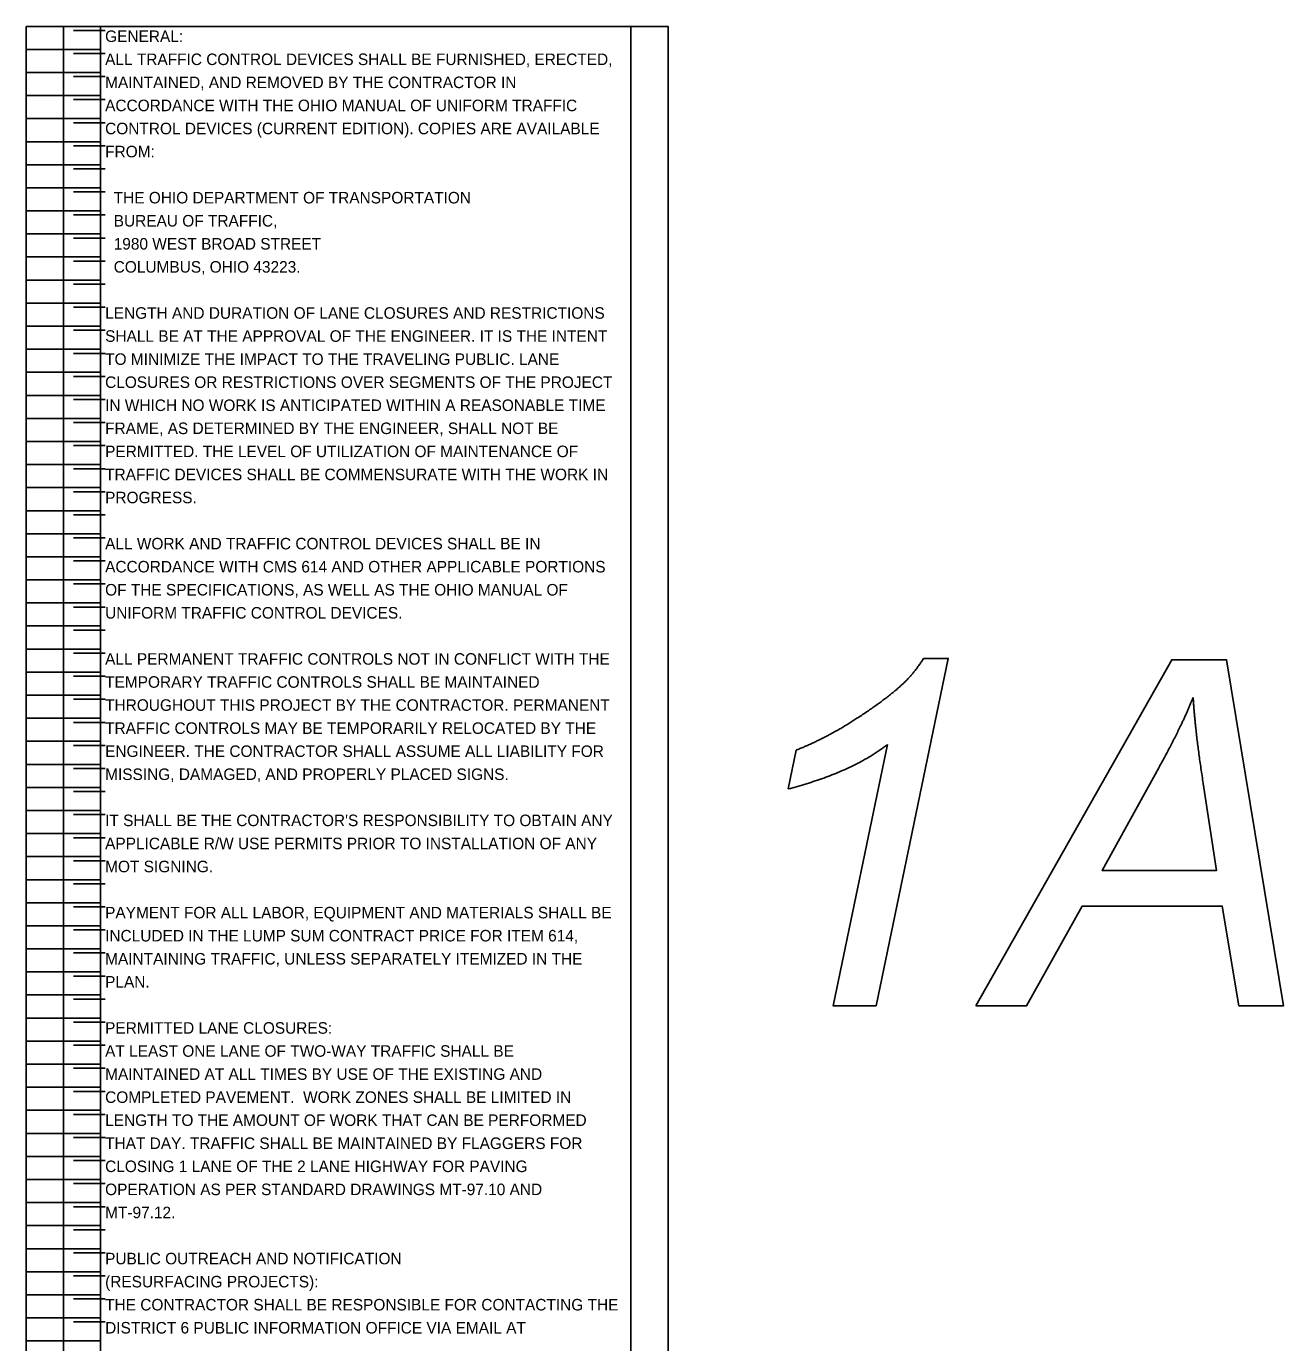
# Model space of a CAD drawing. Extents: x 12522 to 12538, y 1124 to 1850.
# Drawn here: x 12521.92 to 12537.18, y 1833.81 to 1849.79 of the extents above; entities that cross this region are included whole.
import ezdxf

# ---------------------------------------------------------------- set-up
doc = ezdxf.new("R2010")
doc.units = 0
doc.layers.add('SC_Scratch1', color=7, linetype='Continuous')
doc.layers.add('SH_Text', color=7, linetype='Continuous')

msp = doc.modelspace()

# ---------------------------------------------------------------- linework, layer by layer
at = {"layer": 'SC_Scratch1'}
for p, q in [((12521.919, 1829.631), (12521.919, 1849.791)), ((12521.919, 1849.791), (12522.819, 1849.791)), ((12522.876, 1849.741), (12522.492, 1849.741)), ((12522.819, 1829.631), (12522.819, 1849.791)), ((12522.819, 1849.791), (12529.259, 1849.791)), ((12522.819, 1829.631), (12522.819, 1849.791)), ((12522.819, 1849.791), (12522.819, 1829.631)), ((12529.259, 1849.791), (12529.259, 1829.631)), ((12521.919, 1849.511), (12522.819, 1849.511)), ((12522.876, 1849.461), (12522.492, 1849.461)), ((12521.919, 1849.231), (12522.819, 1849.231)), ((12522.876, 1849.181), (12522.492, 1849.181)), ((12521.919, 1848.951), (12522.819, 1848.951)), ((12522.876, 1848.901), (12522.492, 1848.901)), ((12521.919, 1848.671), (12522.819, 1848.671)), ((12522.876, 1848.621), (12522.492, 1848.621)), ((12521.919, 1848.391), (12522.819, 1848.391)), ((12522.876, 1848.341), (12522.492, 1848.341)), ((12521.919, 1848.111), (12522.819, 1848.111)), ((12522.876, 1848.061), (12522.492, 1848.061)), ((12521.919, 1847.831), (12522.819, 1847.831)), ((12522.876, 1847.781), (12522.492, 1847.781)), ((12521.919, 1847.551), (12522.819, 1847.551)), ((12522.876, 1847.501), (12522.492, 1847.501)), ((12521.919, 1847.271), (12522.819, 1847.271)), ((12522.876, 1847.221), (12522.492, 1847.221)), ((12521.919, 1846.991), (12522.819, 1846.991)), ((12522.876, 1846.941), (12522.492, 1846.941)), ((12521.919, 1846.711), (12522.819, 1846.711)), ((12522.876, 1846.661), (12522.492, 1846.661)), ((12521.919, 1846.431), (12522.819, 1846.431)), ((12522.876, 1846.381), (12522.492, 1846.381)), ((12521.919, 1846.151), (12522.819, 1846.151)), ((12522.876, 1846.101), (12522.492, 1846.101)), ((12521.919, 1845.871), (12522.819, 1845.871)), ((12522.876, 1845.821), (12522.492, 1845.821)), ((12521.919, 1845.591), (12522.819, 1845.591)), ((12522.876, 1845.541), (12522.492, 1845.541)), ((12521.919, 1845.311), (12522.819, 1845.311)), ((12522.876, 1845.261), (12522.492, 1845.261)), ((12521.919, 1845.031), (12522.819, 1845.031)), ((12522.876, 1844.981), (12522.492, 1844.981)), ((12521.919, 1844.751), (12522.819, 1844.751)), ((12522.876, 1844.701), (12522.492, 1844.701)), ((12521.919, 1844.471), (12522.819, 1844.471)), ((12522.876, 1844.421), (12522.492, 1844.421)), ((12521.919, 1844.191), (12522.819, 1844.191)), ((12522.876, 1844.141), (12522.492, 1844.141)), ((12521.919, 1843.911), (12522.819, 1843.911)), ((12522.876, 1843.861), (12522.492, 1843.861)), ((12521.919, 1843.631), (12522.819, 1843.631)), ((12522.876, 1843.581), (12522.492, 1843.581)), ((12521.919, 1843.351), (12522.819, 1843.351)), ((12522.876, 1843.301), (12522.492, 1843.301)), ((12521.919, 1843.071), (12522.819, 1843.071)), ((12522.876, 1843.021), (12522.492, 1843.021)), ((12521.919, 1842.791), (12522.819, 1842.791)), ((12522.876, 1842.741), (12522.492, 1842.741)), ((12521.919, 1842.511), (12522.819, 1842.511)), ((12522.876, 1842.461), (12522.492, 1842.461)), ((12521.919, 1842.231), (12522.819, 1842.231)), ((12522.876, 1842.181), (12522.492, 1842.181)), ((12521.919, 1841.951), (12522.819, 1841.951)), ((12522.876, 1841.901), (12522.492, 1841.901)), ((12521.919, 1841.671), (12522.819, 1841.671)), ((12522.876, 1841.621), (12522.492, 1841.621)), ((12521.919, 1841.391), (12522.819, 1841.391)), ((12522.876, 1841.341), (12522.492, 1841.341)), ((12521.919, 1841.111), (12522.819, 1841.111)), ((12522.876, 1841.061), (12522.492, 1841.061)), ((12531.166, 1840.532), (12531.263, 1841.003)), ((12521.919, 1840.831), (12522.819, 1840.831)), ((12522.876, 1840.781), (12522.492, 1840.781)), ((12521.919, 1840.551), (12522.819, 1840.551)), ((12522.876, 1840.501), (12522.492, 1840.501)), ((12521.919, 1840.271), (12522.819, 1840.271)), ((12522.876, 1840.221), (12522.492, 1840.221)), ((12521.919, 1839.991), (12522.819, 1839.991)), ((12522.876, 1839.941), (12522.492, 1839.941)), ((12521.919, 1839.711), (12522.819, 1839.711)), ((12522.876, 1839.661), (12522.492, 1839.661)), ((12521.919, 1839.431), (12522.819, 1839.431)), ((12522.876, 1839.381), (12522.492, 1839.381)), ((12521.919, 1839.151), (12522.819, 1839.151)), ((12522.876, 1839.101), (12522.492, 1839.101)), ((12521.919, 1838.871), (12522.819, 1838.871)), ((12522.876, 1838.821), (12522.492, 1838.821)), ((12521.919, 1838.591), (12522.819, 1838.591)), ((12522.876, 1838.541), (12522.492, 1838.541)), ((12521.919, 1838.311), (12522.819, 1838.311)), ((12522.876, 1838.261), (12522.492, 1838.261)), ((12521.919, 1838.031), (12522.819, 1838.031)), ((12522.876, 1837.981), (12522.492, 1837.981)), ((12521.919, 1837.751), (12522.819, 1837.751)), ((12522.876, 1837.701), (12522.492, 1837.701)), ((12521.919, 1837.471), (12522.819, 1837.471)), ((12522.876, 1837.421), (12522.492, 1837.421)), ((12521.919, 1837.191), (12522.819, 1837.191)), ((12522.876, 1837.141), (12522.492, 1837.141)), ((12521.919, 1836.911), (12522.819, 1836.911)), ((12522.876, 1836.861), (12522.492, 1836.861)), ((12521.919, 1836.631), (12522.819, 1836.631)), ((12522.876, 1836.581), (12522.492, 1836.581)), ((12521.919, 1836.351), (12522.819, 1836.351)), ((12522.876, 1836.301), (12522.492, 1836.301)), ((12521.919, 1836.071), (12522.819, 1836.071)), ((12522.876, 1836.021), (12522.492, 1836.021)), ((12521.919, 1835.791), (12522.819, 1835.791)), ((12522.876, 1835.741), (12522.492, 1835.741)), ((12521.919, 1835.511), (12522.819, 1835.511)), ((12522.876, 1835.461), (12522.492, 1835.461)), ((12521.919, 1835.231), (12522.819, 1835.231)), ((12522.876, 1835.181), (12522.492, 1835.181)), ((12521.919, 1834.951), (12522.819, 1834.951)), ((12522.876, 1834.901), (12522.492, 1834.901)), ((12521.919, 1834.671), (12522.819, 1834.671)), ((12522.876, 1834.621), (12522.492, 1834.621)), ((12521.919, 1834.391), (12522.819, 1834.391)), ((12522.876, 1834.341), (12522.492, 1834.341)), ((12521.919, 1834.111), (12522.819, 1834.111)), ((12522.876, 1834.061), (12522.492, 1834.061)), ((12521.919, 1833.831), (12522.819, 1833.831))]:
    msp.add_line(p, q, dxfattribs=at)
for points in [[(12522.369, 1849.791), (12529.709, 1849.791), (12529.709, 1829.631), (12522.369, 1829.631)], [(12533.445, 1837.901), (12534.061, 1837.901), (12534.737, 1839.111), (12536.436, 1839.111), (12536.638, 1837.901), (12537.182, 1837.901), (12536.489, 1842.101), (12535.824, 1842.101)]]:
    msp.add_lwpolyline(points, close=True, dxfattribs=at)
for points in [[(12532.811, 1842.117), (12533.111, 1842.117), (12532.234, 1837.901), (12531.712, 1837.901), (12532.375, 1841.074)], [(12536.206, 1840.598), (12536.369, 1839.543), (12534.979, 1839.543), (12535.665, 1840.787)]]:
    msp.add_lwpolyline(points, dxfattribs=at)
for points in [[(12532.593, 1841.84), (12532.707, 1841.954), (12532.811, 1842.117)], [(12532.027, 1841.406), (12532.404, 1841.654), (12532.593, 1841.84)], [(12535.665, 1840.787), (12535.94, 1841.282), (12536.084, 1841.643)], [(12536.084, 1841.643), (12536.108, 1841.225), (12536.206, 1840.598)], [(12531.263, 1841.003), (12531.65, 1841.157), (12532.027, 1841.406)], [(12532.375, 1841.074), (12531.945, 1840.736), (12531.166, 1840.532)]]:
    msp.add_open_spline(points, degree=2, dxfattribs=at)

# ---------------------------------------------------------------- texts
at = {"layer": 'SH_Text'}
for s, p in [('GENERAL:', (12522.876, 1849.601)), ('ALL TRAFFIC CONTROL DEVICES SHALL BE FURNISHED, ERECTED,', (12522.876, 1849.321)), ('MAINTAINED, AND REMOVED BY THE CONTRACTOR IN ', (12522.876, 1849.041)), ('ACCORDANCE WITH THE OHIO MANUAL OF UNIFORM TRAFFIC ', (12522.876, 1848.761)), ('CONTROL DEVICES (CURRENT EDITION). COPIES ARE AVAILABLE ', (12522.876, 1848.481)), ('FROM: ', (12522.876, 1848.201)), ('  THE OHIO DEPARTMENT OF TRANSPORTATION ', (12522.876, 1847.641)), ('  BUREAU OF TRAFFIC, ', (12522.876, 1847.361)), ('  1980 WEST BROAD STREET ', (12522.876, 1847.081)), ('  COLUMBUS, OHIO 43223.', (12522.876, 1846.801)), ('LENGTH AND DURATION OF LANE CLOSURES AND RESTRICTIONS ', (12522.876, 1846.241)), ('SHALL BE AT THE APPROVAL OF THE ENGINEER. IT IS THE INTENT ', (12522.876, 1845.961)), ('TO MINIMIZE THE IMPACT TO THE TRAVELING PUBLIC. LANE ', (12522.876, 1845.681)), ('CLOSURES OR RESTRICTIONS OVER SEGMENTS OF THE PROJECT ', (12522.876, 1845.401)), ('IN WHICH NO WORK IS ANTICIPATED WITHIN A REASONABLE TIME ', (12522.876, 1845.121)), ('FRAME, AS DETERMINED BY THE ENGINEER, SHALL NOT BE ', (12522.876, 1844.841)), ('PERMITTED. THE LEVEL OF UTILIZATION OF MAINTENANCE OF ', (12522.876, 1844.561)), ('TRAFFIC DEVICES SHALL BE COMMENSURATE WITH THE WORK IN ', (12522.876, 1844.281)), ('PROGRESS.', (12522.876, 1844.001)), ('ALL WORK AND TRAFFIC CONTROL DEVICES SHALL BE IN ', (12522.876, 1843.441)), ('ACCORDANCE WITH CMS 614 AND OTHER APPLICABLE PORTIONS ', (12522.876, 1843.161)), ('OF THE SPECIFICATIONS, AS WELL AS THE OHIO MANUAL OF ', (12522.876, 1842.881)), ('UNIFORM TRAFFIC CONTROL DEVICES.', (12522.876, 1842.601)), ('ALL PERMANENT TRAFFIC CONTROLS NOT IN CONFLICT WITH THE ', (12522.876, 1842.041)), ('TEMPORARY TRAFFIC CONTROLS SHALL BE MAINTAINED ', (12522.876, 1841.761)), ('THROUGHOUT THIS PROJECT BY THE CONTRACTOR. PERMANENT ', (12522.876, 1841.481)), ('TRAFFIC CONTROLS MAY BE TEMPORARILY RELOCATED BY THE ', (12522.876, 1841.201)), ('ENGINEER. THE CONTRACTOR SHALL ASSUME ALL LIABILITY FOR ', (12522.876, 1840.921)), ('MISSING, DAMAGED, AND PROPERLY PLACED SIGNS.', (12522.876, 1840.641)), ("IT SHALL BE THE CONTRACTOR'S RESPONSIBILITY TO OBTAIN ANY ", (12522.876, 1840.081)), ('APPLICABLE R/W USE PERMITS PRIOR TO INSTALLATION OF ANY ', (12522.876, 1839.801)), ('MOT SIGNING.', (12522.876, 1839.521)), ('PAYMENT FOR ALL LABOR, EQUIPMENT AND MATERIALS SHALL BE ', (12522.876, 1838.961)), ('INCLUDED IN THE LUMP SUM CONTRACT PRICE FOR ITEM 614, ', (12522.876, 1838.681)), ('MAINTAINING TRAFFIC, UNLESS SEPARATELY ITEMIZED IN THE ', (12522.876, 1838.401)), ('PLAN.', (12522.876, 1838.121)), ('PERMITTED LANE CLOSURES:', (12522.876, 1837.561)), ('AT LEAST ONE LANE OF TWO-WAY TRAFFIC SHALL BE ', (12522.876, 1837.281)), ('MAINTAINED AT ALL TIMES BY USE OF THE EXISTING AND ', (12522.876, 1837.001)), ('COMPLETED PAVEMENT.  WORK ZONES SHALL BE LIMITED IN ', (12522.876, 1836.721)), ('LENGTH TO THE AMOUNT OF WORK THAT CAN BE PERFORMED ', (12522.876, 1836.441)), ('THAT DAY. TRAFFIC SHALL BE MAINTAINED BY FLAGGERS FOR ', (12522.876, 1836.161)), ('CLOSING 1 LANE OF THE 2 LANE HIGHWAY FOR PAVING ', (12522.876, 1835.881)), ('OPERATION AS PER STANDARD DRAWINGS MT-97.10 AND ', (12522.876, 1835.601)), ('MT-97.12.', (12522.876, 1835.321)), ('PUBLIC OUTREACH AND NOTIFICATION', (12522.876, 1834.761)), ('(RESURFACING PROJECTS):', (12522.876, 1834.481)), ('THE CONTRACTOR SHALL BE RESPONSIBLE FOR CONTACTING THE ', (12522.876, 1834.201)), ('DISTRICT 6 PUBLIC INFORMATION OFFICE VIA EMAIL AT ', (12522.876, 1833.921))]:
    msp.add_text(s, height=0.14, dxfattribs=at).set_placement(p)

doc.saveas('drawing.dxf')
